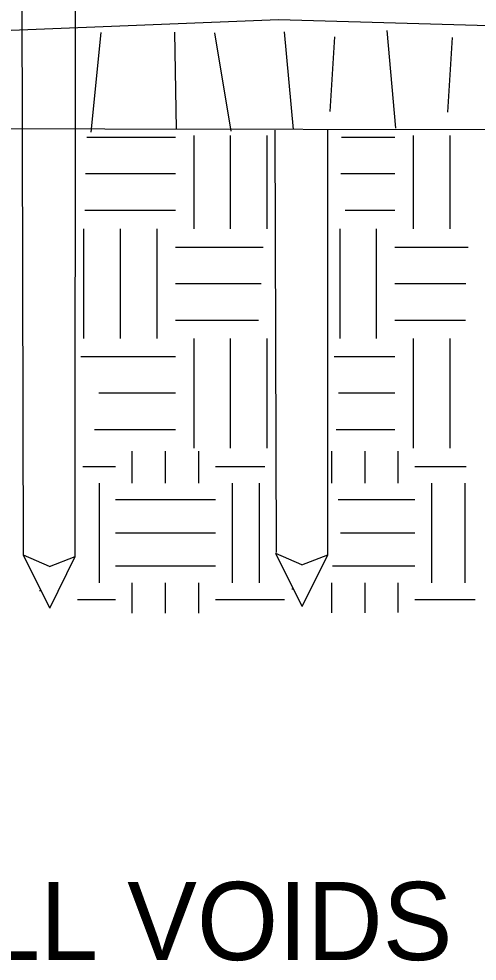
# Model space of a CAD drawing. Extents: x 0 to 2.83, y -0.06 to 1.83.
# Drawn here: x 0.8403 to 0.8916, y 0.8554 to 0.9609 of the extents above; entities that cross this region are included whole.
import ezdxf

# ---------------------------------------------------------------- set-up
doc = ezdxf.new("R2010")
doc.units = 0
for name, color, linetype in [('Edge_of_Truck_Apron', 7, 'Continuous'), ('Existing Grade', 7, 'Continuous'), ('Existing Soil', 7, 'Continuous'), ('Haybales', 7, 'Continuous'), ('Longitudinal Joint', 7, 'Continuous'), ('Wood Stakes', 7, 'Continuous')]:
    doc.layers.add(name, color=color, linetype=linetype)

msp = doc.modelspace()

# ---------------------------------------------------------------- linework, layer by layer
at = {"layer": 'Existing Grade'}
msp.add_lwpolyline([(0.79834, 0.95994), (0.82536, 0.95911), (0.86935, 0.96087), (0.9204, 0.95939), (0.93952, 0.95991)], dxfattribs=at)
at = {"layer": 'Existing Soil'}
for p, q in [((0.85781, 0.94766), (0.8479, 0.94766)), ((0.85781, 0.94766), (0.8479, 0.94766)), ((0.85986, 0.94788), (0.85986, 0.93742)), ((0.85986, 0.94788), (0.85986, 0.93742)), ((0.86395, 0.94788), (0.86395, 0.93742)), ((0.86395, 0.94788), (0.86395, 0.93742)), ((0.86804, 0.94788), (0.86804, 0.93742)), ((0.86804, 0.94788), (0.86804, 0.93742)), ((0.88238, 0.94766), (0.87641, 0.94766)), ((0.88238, 0.94766), (0.87641, 0.94766)), ((0.88442, 0.94788), (0.88442, 0.93742)), ((0.88442, 0.94788), (0.88442, 0.93742)), ((0.88852, 0.94788), (0.88852, 0.93742)), ((0.88852, 0.94788), (0.88852, 0.93742)), ((0.85781, 0.94357), (0.84775, 0.94357)), ((0.85781, 0.94357), (0.84775, 0.94357)), ((0.88238, 0.94357), (0.87631, 0.94357)), ((0.88238, 0.94357), (0.87631, 0.94357)), ((0.85781, 0.93947), (0.84767, 0.93947)), ((0.85781, 0.93947), (0.84767, 0.93947)), ((0.88238, 0.93947), (0.87681, 0.93947)), ((0.88238, 0.93947), (0.87681, 0.93947)), ((0.84757, 0.92514), (0.84757, 0.93742)), ((0.84757, 0.92514), (0.84757, 0.93742)), ((0.85167, 0.92514), (0.85167, 0.93742)), ((0.85167, 0.92514), (0.85167, 0.93742)), ((0.85576, 0.92514), (0.85576, 0.93742)), ((0.85576, 0.92514), (0.85576, 0.93742)), ((0.87623, 0.92514), (0.87623, 0.93742)), ((0.87623, 0.92514), (0.87623, 0.93742)), ((0.88033, 0.92514), (0.88033, 0.93742)), ((0.88033, 0.92514), (0.88033, 0.93742)), ((0.85781, 0.93538), (0.86762, 0.93538)), ((0.85781, 0.93538), (0.86762, 0.93538)), ((0.88238, 0.93538), (0.89058, 0.93538)), ((0.88238, 0.93538), (0.89058, 0.93538)), ((0.85781, 0.93128), (0.86742, 0.93128)), ((0.85781, 0.93128), (0.86742, 0.93128)), ((0.88238, 0.93128), (0.89033, 0.93128)), ((0.88238, 0.93128), (0.89033, 0.93128)), ((0.85781, 0.92719), (0.86711, 0.92719)), ((0.85781, 0.92719), (0.86711, 0.92719)), ((0.88238, 0.92719), (0.89027, 0.92719)), ((0.88238, 0.92719), (0.89027, 0.92719)), ((0.85986, 0.92514), (0.85986, 0.91286)), ((0.85986, 0.92514), (0.85986, 0.91286)), ((0.86395, 0.92514), (0.86395, 0.91286)), ((0.86395, 0.92514), (0.86395, 0.91286)), ((0.86804, 0.92514), (0.86804, 0.91286)), ((0.86804, 0.92514), (0.86804, 0.91286)), ((0.88442, 0.92514), (0.88442, 0.91286)), ((0.88442, 0.92514), (0.88442, 0.91286)), ((0.88852, 0.92514), (0.88852, 0.91286)), ((0.88852, 0.92514), (0.88852, 0.91286)), ((0.85781, 0.92309), (0.84721, 0.92309)), ((0.85781, 0.92309), (0.84721, 0.92309)), ((0.88238, 0.92309), (0.87559, 0.92309)), ((0.88238, 0.92309), (0.87559, 0.92309)), ((0.85781, 0.919), (0.84923, 0.919)), ((0.85781, 0.919), (0.84923, 0.919)), ((0.88238, 0.919), (0.87607, 0.919)), ((0.88238, 0.919), (0.87607, 0.919)), ((0.85781, 0.9149), (0.84875, 0.9149)), ((0.85781, 0.9149), (0.84875, 0.9149)), ((0.88238, 0.9149), (0.87578, 0.9149)), ((0.88238, 0.9149), (0.87578, 0.9149)), ((0.85297, 0.90895), (0.85297, 0.91252)), ((0.85297, 0.90895), (0.85297, 0.91252)), ((0.85669, 0.90895), (0.85669, 0.91252)), ((0.85669, 0.90895), (0.85669, 0.91252)), ((0.86041, 0.90895), (0.86041, 0.91252)), ((0.86041, 0.90895), (0.86041, 0.91252)), ((0.8753, 0.90895), (0.8753, 0.91251)), ((0.8753, 0.90895), (0.8753, 0.91251)), ((0.87903, 0.90895), (0.87903, 0.91251)), ((0.87903, 0.90895), (0.87903, 0.91251)), ((0.88275, 0.90895), (0.88275, 0.91251)), ((0.88275, 0.90895), (0.88275, 0.91251)), ((0.84744, 0.91081), (0.85111, 0.91081)), ((0.84744, 0.91081), (0.85111, 0.91081)), ((0.86228, 0.91081), (0.86781, 0.91081)), ((0.86228, 0.91081), (0.86781, 0.91081)), ((0.88461, 0.91081), (0.89035, 0.91081)), ((0.88461, 0.91081), (0.89035, 0.91081)), ((0.84925, 0.90895), (0.84925, 0.89778)), ((0.84925, 0.90895), (0.84925, 0.89778)), ((0.86414, 0.90895), (0.86414, 0.89778)), ((0.86414, 0.90895), (0.86414, 0.89778)), ((0.86717, 0.90895), (0.86717, 0.89778)), ((0.86717, 0.90895), (0.86717, 0.89778)), ((0.88647, 0.90895), (0.88647, 0.89778)), ((0.88647, 0.90895), (0.88647, 0.89778)), ((0.89019, 0.90895), (0.89019, 0.89778)), ((0.89019, 0.90895), (0.89019, 0.89778)), ((0.86228, 0.90709), (0.85111, 0.90709)), ((0.86228, 0.90709), (0.85111, 0.90709)), ((0.88461, 0.90709), (0.87601, 0.90709)), ((0.88461, 0.90709), (0.87601, 0.90709)), ((0.86228, 0.90336), (0.85111, 0.90336)), ((0.86228, 0.90336), (0.85111, 0.90336)), ((0.88461, 0.90336), (0.8763, 0.90336)), ((0.88461, 0.90336), (0.8763, 0.90336)), ((0.86228, 0.89964), (0.85111, 0.89964)), ((0.86228, 0.89964), (0.85111, 0.89964)), ((0.88461, 0.89964), (0.87539, 0.89964)), ((0.88461, 0.89964), (0.87539, 0.89964)), ((0.85297, 0.89438), (0.85297, 0.89778)), ((0.85297, 0.89438), (0.85297, 0.89778)), ((0.85669, 0.89439), (0.85669, 0.89778)), ((0.85669, 0.89439), (0.85669, 0.89778)), ((0.86041, 0.8944), (0.86041, 0.89778)), ((0.86041, 0.8944), (0.86041, 0.89778)), ((0.8753, 0.89443), (0.8753, 0.89778)), ((0.8753, 0.89443), (0.8753, 0.89778)), ((0.87903, 0.89444), (0.87903, 0.89778)), ((0.87903, 0.89444), (0.87903, 0.89778)), ((0.88275, 0.89445), (0.88275, 0.89778)), ((0.88275, 0.89445), (0.88275, 0.89778)), ((0.84684, 0.89592), (0.85111, 0.89592)), ((0.84684, 0.89592), (0.85111, 0.89592)), ((0.86228, 0.89592), (0.87002, 0.89592)), ((0.86228, 0.89592), (0.87002, 0.89592)), ((0.88461, 0.89592), (0.89134, 0.89592)), ((0.88461, 0.89592), (0.89134, 0.89592))]:
    msp.add_line(p, q, dxfattribs=at)
at = {"layer": 'Haybales'}
for p, q in [((0.84945, 0.9594), (0.84835, 0.94823)), ((0.84945, 0.9594), (0.84835, 0.94823)), ((0.85769, 0.95944), (0.85788, 0.94857)), ((0.85769, 0.95944), (0.85788, 0.94857)), ((0.86217, 0.95937), (0.86399, 0.94837)), ((0.86217, 0.95937), (0.86399, 0.94837)), ((0.86998, 0.95946), (0.87097, 0.94853)), ((0.86998, 0.95946), (0.87097, 0.94853)), ((0.88146, 0.95962), (0.88245, 0.94869)), ((0.88146, 0.95962), (0.88245, 0.94869)), ((0.8756, 0.95893), (0.87509, 0.95057)), ((0.8756, 0.95893), (0.87509, 0.95057)), ((0.88878, 0.95883), (0.88827, 0.95047)), ((0.88878, 0.95883), (0.88827, 0.95047))]:
    msp.add_line(p, q, dxfattribs=at)
for points in [[(0.79834, 0.95994), (0.82536, 0.95911), (0.86935, 0.96087), (0.9204, 0.95939), (0.93952, 0.95991)], [(0.80554, 0.94868), (0.9386, 0.94845), (0.95055, 0.94868)], [(0.80554, 0.94868), (0.9386, 0.94845), (0.95055, 0.94868)]]:
    msp.add_lwpolyline(points, dxfattribs=at)
at = {"layer": 'Longitudinal Joint'}
for p, q in [((0.8466, 0.90073), (0.84662, 0.98735)), ((0.87485, 0.90087), (0.87486, 0.94856)), ((0.86911, 0.90116), (0.86896, 0.94848)), ((0.84373, 0.89494), (0.84078, 0.90088)), ((0.84369, 0.89962), (0.84078, 0.90088)), ((0.84369, 0.89962), (0.8466, 0.90072)), ((0.84373, 0.89494), (0.8466, 0.90072)), ((0.87194, 0.8998), (0.86903, 0.90106)), ((0.87198, 0.89512), (0.86903, 0.90106)), ((0.87194, 0.8998), (0.87485, 0.9009)), ((0.87198, 0.89512), (0.87485, 0.9009)), ((0.84277, 0.89688), (0.84259, 0.89688)), ((0.84277, 0.89688), (0.84259, 0.89688)), ((0.87102, 0.89706), (0.87084, 0.89706)), ((0.87102, 0.89706), (0.87084, 0.89706))]:
    msp.add_line(p, q, dxfattribs=at)
at = {"layer": 'Wood Stakes'}
for p, q in [((0.8466, 0.90073), (0.84662, 0.98735)), ((0.84078, 0.90088), (0.84061, 0.97575)), ((0.87485, 0.90087), (0.87486, 0.94856)), ((0.86911, 0.90116), (0.86896, 0.94848)), ((0.84373, 0.89494), (0.84078, 0.90088)), ((0.84369, 0.89962), (0.84078, 0.90088)), ((0.84369, 0.89962), (0.8466, 0.90072)), ((0.84373, 0.89494), (0.8466, 0.90072)), ((0.87194, 0.8998), (0.86903, 0.90106)), ((0.87198, 0.89512), (0.86903, 0.90106)), ((0.87194, 0.8998), (0.87485, 0.9009)), ((0.87198, 0.89512), (0.87485, 0.9009))]:
    msp.add_line(p, q, dxfattribs=at)

# ---------------------------------------------------------------- texts
at = {"layer": 'Edge_of_Truck_Apron'}
msp.add_text('FILL VOIDS ', height=0.00875, dxfattribs=at).set_placement((0.82574, 0.85554))

doc.saveas('drawing.dxf')
